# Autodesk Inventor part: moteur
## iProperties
Created: 2009-09
Part Number: moteur
Document SubType Name: Modeling
Designer: Olivier
Density: 1 g/cm^3
Author: Olivier
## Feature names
1. Extrusion1
2. Extrusion3
3. Congé2 [Fillet]
4. Congé3 [Fillet]
5. Extrusion4
6. Congé4 [Fillet]
7. Extrusion5
8. Extrusion6
9. Extrusion7
10. Extrusion8
11. Congé6 [Fillet]
12. Miroir1 [Mirror]
13. Révolution1 [Revolution]
14. Chanfrein1 [Chamfer]
15. Congé7 [Fillet]
16. Congé8 [Fillet]
17. Extrusion9
18. Congé9 [Fillet]
19. Réseau circulaire1 [Circular Pattern]
20. Congé10 [Fillet]
21. Extrusion10
22. Extrusion11
23. Miroir2 [Mirror]
24. Congé11 [Fillet]
25. Extrusion13
26. Extrusion14
27. Extrusion15
28. Extrusion16
29. Congé12 [Fillet]
30. Extrusion17
31. Congé13 [Fillet]
32. Extrusion18
33. Extrusion19
34. Extrusion20
35. Chanfrein2 [Chamfer]
36. Extrusion12
